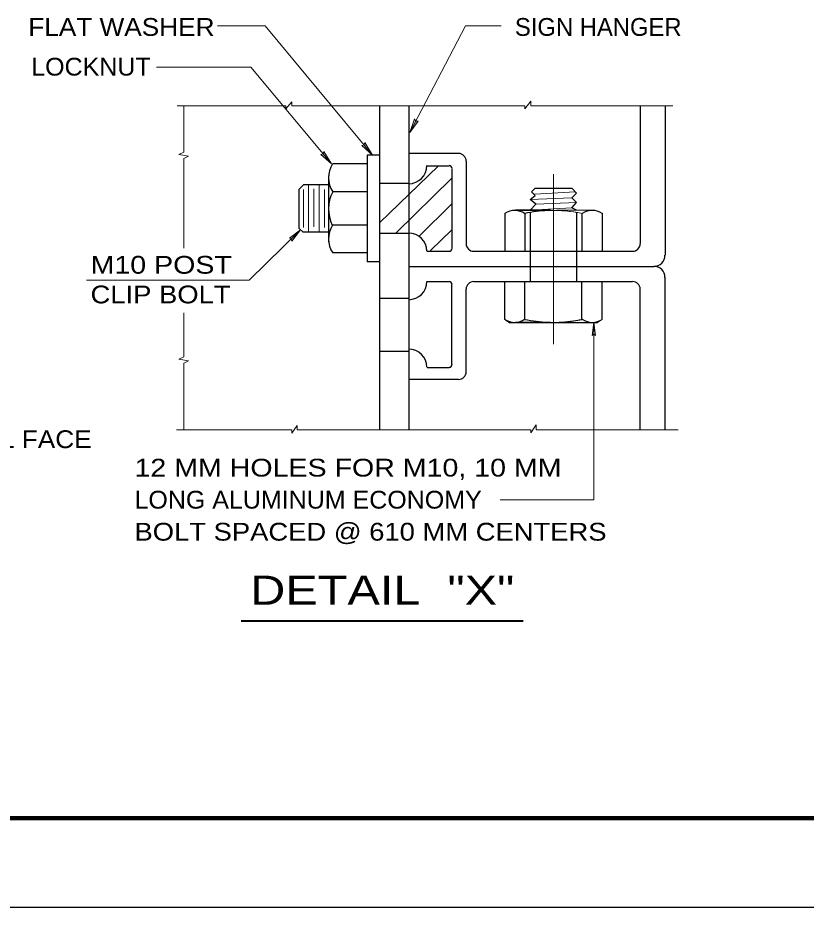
# Model space of a CAD drawing. Extents: x 312601.858 to 312602.699, y 144420.109 to 144420.704.
# Drawn here: x 312602.3741 to 312602.507, y 144420.1095 to 144420.2594 of the extents above; entities that cross this region are included whole.
import ezdxf

# ---------------------------------------------------------------- set-up
doc = ezdxf.new("R2010")
doc.units = 0
doc.header["$LTSCALE"] = 0.0012
for name, pattern in [('DOT_DASHED', [7.7, 5, -1.2, 0.3, -1.2]), ('LONG_DASHED', [7.5, 6, -1.5]), ('MEDIUM_DASHED', [4.5, 3, -1.5])]:
    doc.linetypes.add(name, pattern=pattern)
for name, color, linetype, lineweight in [('1', 7, 'Continuous', 13), ('2', 7, 'Continuous', 13), ('39', 7, 'Continuous', 13)]:
    doc.layers.add(name, color=color, linetype=linetype, lineweight=lineweight)

msp = doc.modelspace()

# ---------------------------------------------------------------- hatches: boundary and pattern name
at = {"layer": '39'}
for points in [[(312602.4412, 144420.242), (312602.4416, 144420.242), (312602.4402, 144420.2401), (312602.441, 144420.2424)], [(312602.4325, 144420.238), (312602.4326, 144420.2384), (312602.4339, 144420.2363), (312602.4321, 144420.2379)], [(312602.4256, 144420.2365), (312602.4257, 144420.2369), (312602.427, 144420.2348), (312602.4252, 144420.2364)], [(312602.4202, 144420.2222), (312602.4199, 144420.2223), (312602.4218, 144420.2237), (312602.4203, 144420.2218)]]:
    msp.add_hatch(color=256, dxfattribs=at).paths.add_polyline_path(points)

# ---------------------------------------------------------------- linework, layer by layer
at = {"layer": '1'}
for p, q in [((312602.4078, 144420.2581), (312602.4158, 144420.2581)), ((312602.4496, 144420.2581), (312602.4556, 144420.2581)), ((312602.3975, 144420.2511), (312602.4134, 144420.2511)), ((312602.401, 144420.2446), (312602.4193, 144420.2446)), ((312602.4021, 144420.2446), (312602.4021, 144420.2368)), ((312602.4193, 144420.2441), (312602.4203, 144420.2453)), ((312602.4193, 144420.2441), (312602.4193, 144420.2446)), ((312602.4203, 144420.2446), (312602.4203, 144420.2453)), ((312602.4203, 144420.2446), (312602.4596, 144420.2446)), ((312602.4596, 144420.2441), (312602.4606, 144420.2454)), ((312602.4596, 144420.2441), (312602.4596, 144420.2446)), ((312602.4606, 144420.2446), (312602.4606, 144420.2454)), ((312602.4606, 144420.2446), (312602.4845, 144420.2446)), ((312602.4013, 144420.2364), (312602.4021, 144420.2368)), ((312602.4013, 144420.2364), (312602.4029, 144420.2361)), ((312602.4021, 144420.2357), (312602.4029, 144420.2361)), ((312602.4021, 144420.2357), (312602.4021, 144420.2206)), ((312602.4351, 144420.2249), (312602.445, 144420.2345)), ((312602.4379, 144420.2232), (312602.4473, 144420.2324)), ((312602.4231, 144420.2313), (312602.4231, 144420.2233)), ((312602.424, 144420.2306), (312602.424, 144420.2242)), ((312602.4249, 144420.2313), (312602.4249, 144420.2233)), ((312602.4223, 144420.2305), (312602.4223, 144420.2241)), ((312602.4258, 144420.2305), (312602.4258, 144420.2241)), ((312602.4605, 144420.2288), (312602.4675, 144420.2291)), ((312602.4612, 144420.2297), (312602.4681, 144420.2301)), ((312602.4417, 144420.2226), (312602.4473, 144420.2281)), ((312602.4614, 144420.228), (312602.4683, 144420.2283)), ((312602.4605, 144420.227), (312602.4675, 144420.2274)), ((312602.4649, 144420.227), (312602.4708, 144420.227)), ((312602.4437, 144420.2202), (312602.4473, 144420.2237)), ((312602.4131, 144420.2152), (312602.3857, 144420.2152)), ((312602.4021, 144420.2097), (312602.4021, 144420.2023)), ((312602.4649, 144420.2081), (312602.4708, 144420.2081)), ((312602.4725, 144420.2085), (312602.4718, 144420.2081)), ((312602.4013, 144420.2019), (312602.4021, 144420.2023)), ((312602.4013, 144420.2019), (312602.4029, 144420.2016)), ((312602.4021, 144420.2012), (312602.4029, 144420.2016)), ((312602.4021, 144420.2012), (312602.4021, 144420.19)), ((312602.4203, 144420.1894), (312602.4212, 144420.1907)), ((312602.4212, 144420.19), (312602.4212, 144420.1907)), ((312602.4606, 144420.1895), (312602.4615, 144420.1908)), ((312602.4615, 144420.19), (312602.4615, 144420.1908)), ((312602.4009, 144420.19), (312602.4203, 144420.19)), ((312602.4203, 144420.1894), (312602.4203, 144420.19)), ((312602.4212, 144420.19), (312602.4606, 144420.19)), ((312602.4606, 144420.1895), (312602.4606, 144420.19)), ((312602.4615, 144420.19), (312602.4854, 144420.19))]:
    msp.add_line(p, q, dxfattribs=at)
at = {"layer": '1', "lineweight": 25}
for p, q in [((312602.4351, 144420.2446), (312602.4351, 144420.19)), ((312602.44, 144420.2446), (312602.44, 144420.19)), ((312602.479, 144420.2446), (312602.479, 144420.2214)), ((312602.4832, 144420.2446), (312602.4832, 144420.2194)), ((312602.44, 144420.2366), (312602.4484, 144420.2366)), ((312602.433, 144420.2363), (312602.433, 144420.2183)), ((312602.4497, 144420.2353), (312602.4497, 144420.2214)), ((312602.4431, 144420.2345), (312602.4468, 144420.2345)), ((312602.4473, 144420.234), (312602.4473, 144420.2206)), ((312602.4265, 144420.2328), (312602.4265, 144420.2217)), ((312602.4607, 144420.2301), (312602.4613, 144420.2307)), ((312602.4613, 144420.2307), (312602.4675, 144420.2307)), ((312602.4683, 144420.2299), (312602.4675, 144420.2307)), ((312602.4215, 144420.2305), (312602.4215, 144420.224)), ((312602.4562, 144420.2265), (312602.4562, 144420.2201)), ((312602.4639, 144420.227), (312602.458, 144420.227)), ((312602.4596, 144420.2265), (312602.4596, 144420.2201)), ((312602.4683, 144420.227), (312602.4675, 144420.2274)), ((312602.4692, 144420.2265), (312602.4692, 144420.2201)), ((312602.4726, 144420.2265), (312602.4726, 144420.2201)), ((312602.4431, 144420.2201), (312602.4468, 144420.2201)), ((312602.451, 144420.2201), (312602.4777, 144420.2201)), ((312602.44, 144420.2175), (312602.4813, 144420.2175)), ((312602.4832, 144420.19), (312602.4832, 144420.2157)), ((312602.4431, 144420.215), (312602.4468, 144420.215)), ((312602.4473, 144420.201), (312602.4473, 144420.2145)), ((312602.451, 144420.215), (312602.4777, 144420.215)), ((312602.4562, 144420.2086), (312602.4562, 144420.215)), ((312602.4596, 144420.2086), (312602.4596, 144420.215)), ((312602.4692, 144420.2086), (312602.4692, 144420.215)), ((312602.4726, 144420.2087), (312602.4726, 144420.215)), ((312602.4497, 144420.1998), (312602.4497, 144420.2137)), ((312602.479, 144420.19), (312602.479, 144420.2137)), ((312602.44, 144420.2121), (312602.4351, 144420.2121)), ((312602.4563, 144420.2085), (312602.457, 144420.2081)), ((312602.457, 144420.2081), (312602.458, 144420.2081)), ((312602.4639, 144420.2081), (312602.458, 144420.2081)), ((312602.4639, 144420.2081), (312602.4718, 144420.2081)), ((312602.44, 144420.2032), (312602.4351, 144420.2032)), ((312602.4431, 144420.2005), (312602.4468, 144420.2005)), ((312602.44, 144420.1985), (312602.4484, 144420.1985))]:
    msp.add_line(p, q, dxfattribs=at)
at = {"layer": '1', "linetype": 'DOT_DASHED'}
msp.add_line((312602.4644, 144420.2044), (312602.4644, 144420.2331), dxfattribs=at)
at = {"layer": '1', "linetype": 'MEDIUM_DASHED', "lineweight": 25}
for p, q in [((312602.44, 144420.2315), (312602.4351, 144420.2315)), ((312602.44, 144420.2231), (312602.4351, 144420.2231))]:
    msp.add_line(p, q, dxfattribs=at)
at = {"layer": '1', "linetype": 'LONG_DASHED', "lineweight": 25}
for p, q in [((312602.4605, 144420.2266), (312602.4605, 144420.215)), ((312602.4683, 144420.2266), (312602.4683, 144420.215))]:
    msp.add_line(p, q, dxfattribs=at)
at = {"layer": '1', "lineweight": 25}
for points in [[(312602.4605, 144420.227), (312602.4614, 144420.228), (312602.4605, 144420.2288), (312602.4613, 144420.2295), (312602.4607, 144420.2301)], [(312602.4675, 144420.2274), (312602.4683, 144420.2283), (312602.4675, 144420.2291), (312602.4683, 144420.2299)], [(312602.4639, 144420.227), (312602.4581, 144420.227), (312602.4639, 144420.227)], [(312602.4639, 144420.2081), (312602.4581, 144420.2081), (312602.4639, 144420.2081)]]:
    msp.add_lwpolyline(points, dxfattribs=at)
at = {"layer": '1'}
for points in [[(312602.4649, 144420.227), (312602.4707, 144420.227), (312602.4649, 144420.227)], [(312602.4712, 144420.2081), (312602.4712, 144420.1782), (312602.4554, 144420.1782)], [(312602.4649, 144420.2081), (312602.4707, 144420.2081), (312602.4649, 144420.2081)]]:
    msp.add_lwpolyline(points, dxfattribs=at)
at = {"layer": '1', "linetype": 'LONG_DASHED', "lineweight": 25}
msp.add_lwpolyline([(312602.4581, 144420.2081), (312602.4639, 144420.2081), (312602.4581, 144420.2081)], dxfattribs=at)
at = {"layer": '1'}
msp.add_lwpolyline([(312602.4709, 144420.2059), (312602.4712, 144420.2081), (312602.4715, 144420.2059), (312602.4712, 144420.2061)], close=True, dxfattribs=at)
at = {"layer": '1', "lineweight": 25}
for centre, radius, start, end in [((312602.448415, 144420.235295), 0.001275, 0, 90), ((312602.44, 144420.23453), 0.00306, 270, 0), ((312602.4468, 144420.23402), 0.00051, 0, 90), ((312602.45785, 144420.22399), 0.002975, 88.37341, 123.68467), ((312602.45785, 144420.22399), 0.002975, 55.64684, 86.74614), ((312602.464395, 144420.203696), 0.023269, 92.30038, 102.01801), ((312602.47094, 144420.22399), 0.002975, 56.08356, 124.66567), ((312602.44, 144420.22008), 0.00306, 0, 90), ((312602.4468, 144420.22059), 0.00051, 270, 0), ((312602.450965, 144420.221355), 0.001275, 180, 270), ((312602.47774, 144420.221355), 0.001275, 270, 0), ((312602.48131, 144420.2194), 0.00187, 270, 0), ((312602.48131, 144420.21566), 0.00187, 0, 90), ((312602.44, 144420.21498), 0.00306, 270, 0), ((312602.4468, 144420.21447), 0.00051, 0, 90), ((312602.450965, 144420.213705), 0.001275, 90, 180), ((312602.47774, 144420.213705), 0.001275, 0, 90), ((312602.45785, 144420.21107), 0.002975, 235.15009, 271.62659), ((312602.45785, 144420.21107), 0.002975, 273.25386, 304.35316), ((312602.464395, 144420.231364), 0.023269, 257.98199, 267.69962), ((312602.464395, 144420.231364), 0.023269, 267.87557, 281.99656), ((312602.47094, 144420.21107), 0.002975, 235.33433, 304.84991), ((312602.44, 144420.20053), 0.00306, 0, 90), ((312602.4468, 144420.20104), 0.00051, 270, 0), ((312602.448415, 144420.199765), 0.001275, 270, 0)]:
    msp.add_arc(centre, radius, start, end, dxfattribs=at)
at = {"layer": '1'}
for centre, radius, start, end in [((312602.464395, 144420.203696), 0.023269, 78.00344, 92.12443), ((312602.464395, 144420.203696), 0.023269, 77.98199, 87.69962), ((312602.47094, 144420.22399), 0.002975, 93.25386, 124.35316), ((312602.464395, 144420.231364), 0.023269, 272.30038, 282.01801), ((312602.47094, 144420.21107), 0.002975, 235.64684, 266.74614)]:
    msp.add_arc(centre, radius, start, end, dxfattribs=at)
at = {"layer": '2'}
for p, q in [((312602.4339, 144420.2363), (312602.4158, 144420.2581)), ((312602.4402, 144420.2401), (312602.4496, 144420.2581)), ((312602.427, 144420.2348), (312602.4134, 144420.2511)), ((312602.4131, 144420.2152), (312602.4218, 144420.2237))]:
    msp.add_line(p, q, dxfattribs=at)
at = {"layer": '2', "lineweight": 25}
for p, q in [((312602.4351, 144420.2363), (312602.433, 144420.2363)), ((312602.433, 144420.2348), (312602.4272, 144420.2348)), ((312602.4215, 144420.2305), (312602.4223, 144420.2313)), ((312602.4265, 144420.2313), (312602.4223, 144420.2313)), ((312602.433, 144420.2301), (312602.4272, 144420.2301)), ((312602.4215, 144420.224), (312602.4222, 144420.2233)), ((312602.4265, 144420.2233), (312602.4222, 144420.2233)), ((312602.433, 144420.2245), (312602.4271, 144420.2245)), ((312602.433, 144420.2198), (312602.4272, 144420.2198)), ((312602.4351, 144420.2183), (312602.433, 144420.2183))]:
    msp.add_line(p, q, dxfattribs=at)
at = {"layer": '2', "lineweight": 40}
msp.add_line((312602.4118, 144420.1578), (312602.4593, 144420.1578), dxfattribs=at)
at = {"layer": '2', "lineweight": 25}
for centre, radius, start, end in [((312602.43089, 144420.232481), 0.004392, 148.13408, 212.83301), ((312602.432834, 144420.227198), 0.006338, 152.75314, 205.20079), ((312602.43089, 144420.222181), 0.004392, 148.13408, 212.83301)]:
    msp.add_arc(centre, radius, start, end, dxfattribs=at)
at = {"layer": '39', "lineweight": 158}
msp.add_line((312601.9088, 144420.1245), (312602.6838, 144420.1245), dxfattribs=at)
at = {"layer": '39', "lineweight": 25}
for p, q in [((312602.452, 144420.1245), (312602.6838, 144420.1245)), ((312601.8578, 144420.1095), (312602.6988, 144420.1095))]:
    msp.add_line(p, q, dxfattribs=at)
at = {"layer": '39'}
for points in [[(312602.4412, 144420.242), (312602.4416, 144420.242), (312602.4402, 144420.2401), (312602.441, 144420.2424)], [(312602.4325, 144420.238), (312602.4326, 144420.2384), (312602.4339, 144420.2363), (312602.4321, 144420.2379)], [(312602.4256, 144420.2365), (312602.4257, 144420.2369), (312602.427, 144420.2348), (312602.4252, 144420.2364)], [(312602.4202, 144420.2222), (312602.4199, 144420.2223), (312602.4218, 144420.2237), (312602.4203, 144420.2218)]]:
    msp.add_lwpolyline(points, close=True, dxfattribs=at)

# ---------------------------------------------------------------- texts
at = {"layer": '2'}
for s, height, width, p in [('FLAT WASHER', 0.003, 1.1, (312602.3759, 144420.2564)), ('LOCKNUT', 0.003, 1.05, (312602.3764, 144420.2497)), ('M10 POST ', 0.003, 1.2, (312602.3864, 144420.2163)), ('CLIP BOLT', 0.003, 1.15, (312602.3864, 144420.2113)), ('SIGN PANEL FACE', 0.003, 1.1, (312602.3471, 144420.1869)), ('12 MM HOLES FOR M10, 10 MM ', 0.003, 1.2, (312602.3938, 144420.1821)), ('LONG ALUMINUM ECONOMY', 0.003, 1.05, (312602.3938, 144420.1767)), ('BOLT SPACED @ 610 MM CENTERS', 0.003, 1.15, (312602.3938, 144420.1713)), ('DETAIL  "X"', 0.0049, 1.25, (312602.4133, 144420.1605))]:
    msp.add_text(s, height=height, dxfattribs=dict(at, width=width)).set_placement(p)
msp.add_text('SIGN HANGER', height=0.003, dxfattribs=at).set_placement((312602.4579, 144420.2564))

doc.saveas('drawing.dxf')
